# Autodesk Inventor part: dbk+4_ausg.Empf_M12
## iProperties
Created: 2010-01
Part Number: dbk+4_ausg.Empf_M12
Document SubType Name: Modeling
Designer: Oliver Liedtke
Density: 1 g/cm^3
Author: Oliver Liedtke
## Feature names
1. Umdrehung1 [Revolution]
